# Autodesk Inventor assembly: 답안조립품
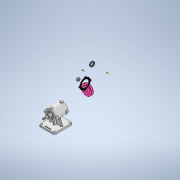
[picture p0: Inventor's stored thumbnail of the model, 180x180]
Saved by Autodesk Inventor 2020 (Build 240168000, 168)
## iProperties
Created: 2022-11
Part Number: 답안조립품
Document SubType Name: Assembly
Designer: owner
Author: owner
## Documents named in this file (12)
- C:\Users\owner\Desktop\721108V1019\답안조립품.iam
- C:\Users\owner\Desktop\721108V1019\본체.ipt
- C:\Users\owner\Desktop\721108V1019\V-벨트풀리.ipt
- C:\Users\owner\Desktop\721108V1019\개스킷.ipt
- C:\Users\owner\Desktop\721108V1019\너트 M12 x 1.25.ipt
- C:\Users\owner\Desktop\721108V1019\뒤커버.ipt
- C:\Users\owner\Desktop\721108V1019\베어링 6204.ipt
- C:\Users\owner\Desktop\721108V1019\볼트 M4 x 12.ipt
- C:\Users\owner\Desktop\721108V1019\앞커버.ipt
- C:\Users\owner\Desktop\721108V1019\오일 실.ipt
- C:\Users\owner\Desktop\721108V1019\축.ipt
- C:\Users\owner\Desktop\721108V1019\키 4 x 4.ipt
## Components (7 placed, 6 different names)
1. V-벨트풀리:1
2. 개스킷:1
3. KS B 1012 클래스 1 일반 - 미터 M12x1.25:1
4. KS B 2023 6204 - 20 x 47 x 14:1
5. KS B 2804 D D - 20 32 8:1
6. KS B 1311 (I) 4 x 4 x 12:1
7. KS B 2023 6204 - 20 x 47 x 14:2
